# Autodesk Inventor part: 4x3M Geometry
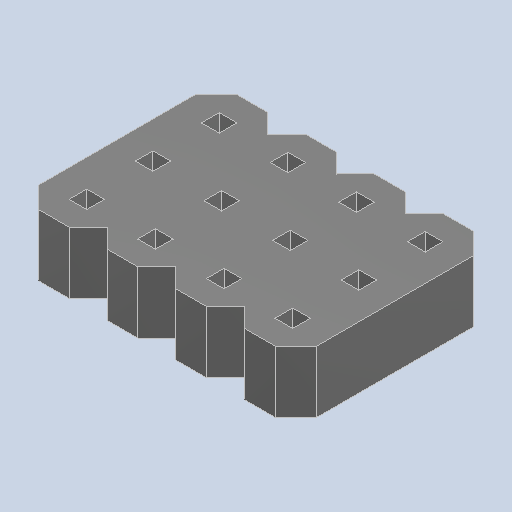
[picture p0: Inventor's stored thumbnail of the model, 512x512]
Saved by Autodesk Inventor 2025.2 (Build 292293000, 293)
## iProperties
Created: 2025-04
Part Number: 4x3M Geometry
Material: Generic
Description: PART-4x3M Geometry-DESC
Document SubType Name: Modeling
Designer: BennF
Density: 1 g/cm^3
Appearance: Default
Author: BennF
Revision Number: NONE
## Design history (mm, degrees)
feature "4x3"
body "Solid1"
